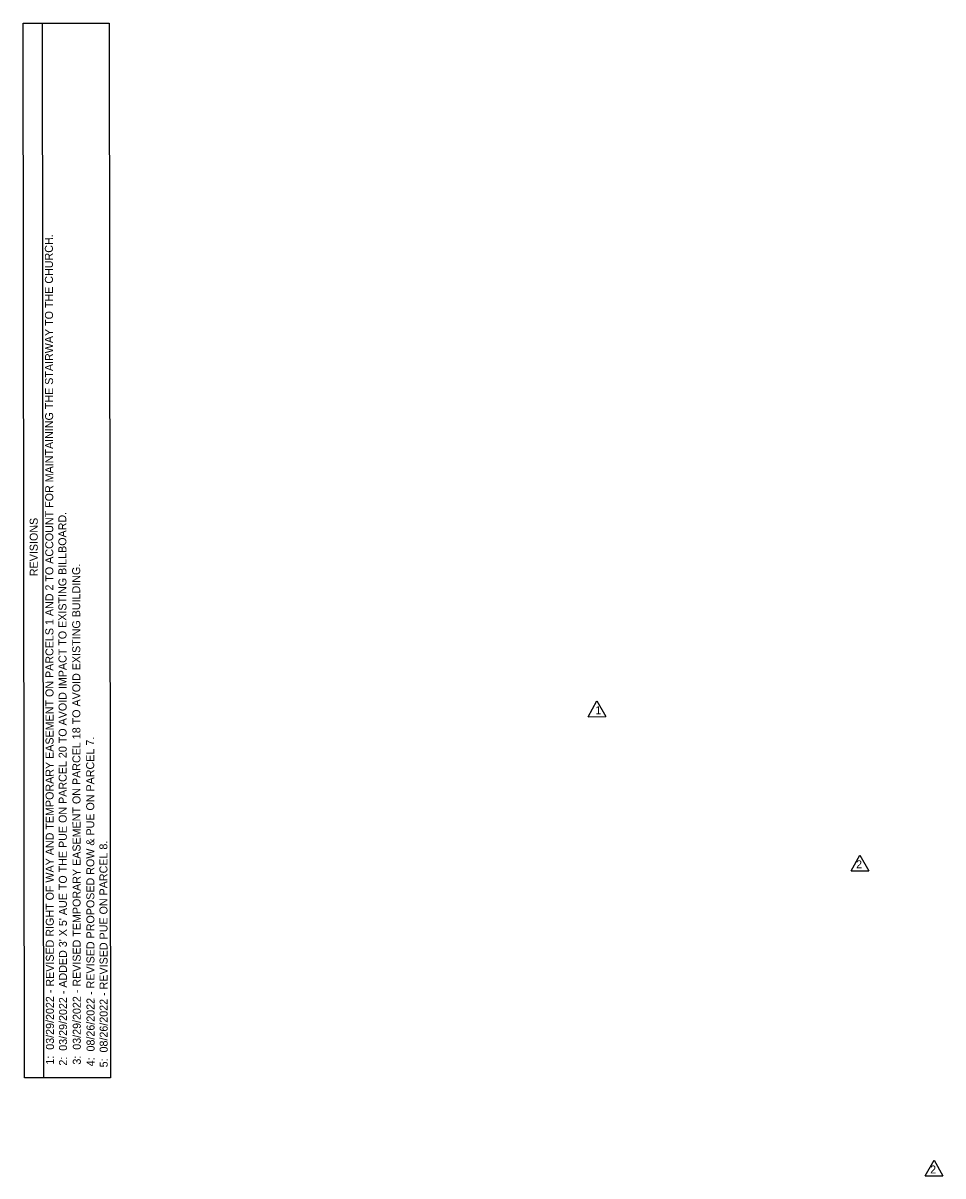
# Model space of a CAD drawing. Extents: x 1882804 to 1884487, y 844572 to 845443.
# Drawn here: x 1882804 to 1883494, y 844572 to 845437 of the extents above; entities that cross this region are included whole.
import ezdxf

# ---------------------------------------------------------------- set-up
doc = ezdxf.new("R2010")
doc.units = 0
doc.layers.add('Sheet Block Revision CELL', color=7, linetype='Continuous')

msp = doc.modelspace()

# ---------------------------------------------------------------- linework, layer by layer
at = {"layer": 'Sheet Block Revision CELL'}
for p, q in [((1882819.72, 844645.93), (1882818.66, 845436.56)), ((1883227.75, 844916.7), (1883234.33, 844928.46)), ((1883234.33, 844928.46), (1883241, 844916.75)), ((1883227.75, 844916.7), (1883241, 844916.75)), ((1883424.95, 844801.18), (1883431.53, 844812.94)), ((1883431.53, 844812.94), (1883438.19, 844801.23)), ((1883424.95, 844801.18), (1883438.19, 844801.23)), ((1883480.48, 844572.46), (1883487.06, 844584.22)), ((1883487.06, 844584.22), (1883493.72, 844572.51)), ((1883480.48, 844572.46), (1883493.72, 844572.51))]:
    msp.add_line(p, q, dxfattribs=at)
msp.add_lwpolyline([(1882805.17, 844645.9), (1882804.13, 845436.53), (1882868.56, 845436.62), (1882869.6, 844645.99)], close=True, dxfattribs=at)

# ---------------------------------------------------------------- texts
for s, rotation, p in [('1:  03/29/2022 - REVISED RIGHT OF WAY AND TEMPORARY EASEMENT ON PARCELS 1 AND 2 TO ACCOUNT FOR MAINTAINING THE STAIRWAY TO THE CHURCH.', 90.07577, (1882827.3, 844655.91)), ('REVISIONS', 90.07577, (1882815.17, 845022.07)), ("2:  03/29/2022 - ADDED 3' X 5' AUE TO THE PUE ON PARCEL 20 TO AVOID IMPACT TO EXISTING BILLBOARD.", 90.07577, (1882837.11, 844655.16)), ('3:  03/29/2022 - REVISED TEMPORARY EASEMENT ON PARCEL 18 TO AVOID EXISTING BUILDING.', 90.07577, (1882847.43, 844655.91)), ('1', 0.22076, (1883233.18, 844918.53)), ('4:  08/26/2022 - REVISED PROPOSED ROW & PUE ON PARCEL 7.', 90.07577, (1882857.75, 844654.61)), ('5:  08/26/2022 - REVISED PUE ON PARCEL 8.', 90.07577, (1882867.57, 844653.86)), ('2', 0.22076, (1883428.63, 844803.01)), ('2', 0.22076, (1883484.16, 844574.29))]:
    msp.add_text(s, height=6, rotation=rotation, dxfattribs=at).set_placement(p)

doc.saveas('drawing.dxf')
